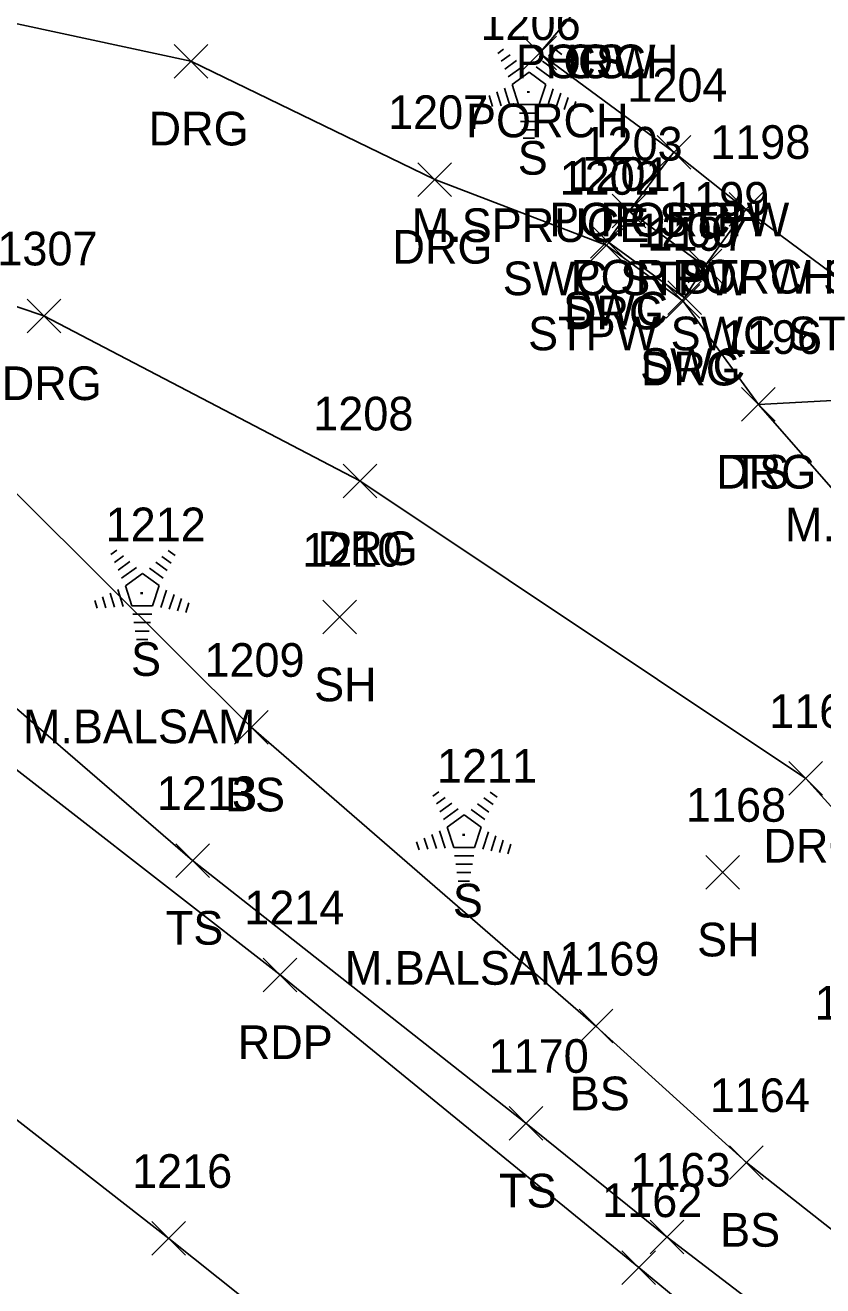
# Model space of a CAD drawing. Extents: x 1537342 to 1542195, y 163002 to 168596.
# Drawn here: x 1541938.8 to 1541986.2, y 163219.8 to 163294.7 of the extents above; entities that cross this region are included whole.
import ezdxf

# ---------------------------------------------------------------- set-up
doc = ezdxf.new("R2010")
doc.units = 0
for name, color, linetype in [('L_A', 7, 'Continuous'), ('L_C', 7, 'Continuous'), ('L_I', 7, 'Continuous'), ('L_TIC', 7, 'Continuous'), ('LBF', 7, 'Continuous'), ('LELB', 7, 'Continuous'), ('LTC', 7, 'Continuous'), ('P_A', 7, 'Continuous'), ('P_I', 7, 'Continuous'), ('P_TIC', 7, 'Continuous'), ('PET', 7, 'Continuous'), ('PRC', 7, 'Continuous'), ('R_A', 7, 'Continuous'), ('R_I', 7, 'Continuous'), ('R_TIC', 7, 'Continuous'), ('RDG', 7, 'Continuous'), ('RSW', 7, 'Continuous')]:
    doc.layers.add(name, color=color, linetype=linetype)

msp = doc.modelspace()

# ---------------------------------------------------------------- linework, layer by layer
at = {"layer": 'L_TIC'}
for points in [[(1541968.383, 163291.994), (1541970.383, 163293.994)], [(1541970.383, 163291.994), (1541968.383, 163293.994)], [(1541976.366, 163286.102), (1541978.366, 163288.102)], [(1541978.366, 163286.102), (1541976.366, 163288.102)], [(1541976.366, 163286.102), (1541978.366, 163288.102)], [(1541978.366, 163286.102), (1541976.366, 163288.102)], [(1541973.702, 163282.614), (1541975.702, 163284.614)], [(1541975.702, 163282.614), (1541973.702, 163284.614)], [(1541980.643, 163282.712), (1541982.643, 163284.712)], [(1541982.643, 163282.712), (1541980.643, 163284.712)], [(1541980.643, 163282.712), (1541982.643, 163284.712)], [(1541982.643, 163282.712), (1541980.643, 163284.712)], [(1541978.208, 163279.339), (1541980.208, 163281.339)], [(1541980.208, 163279.339), (1541978.208, 163281.339)], [(1541981.386, 163271.123), (1541983.386, 163273.123)], [(1541983.386, 163271.123), (1541981.386, 163273.123)], [(1541956.494, 163258.485), (1541958.494, 163260.485)], [(1541958.494, 163258.485), (1541956.494, 163260.485)], [(1541951.245, 163251.94), (1541953.245, 163253.94)], [(1541953.245, 163251.94), (1541951.245, 163253.94)], [(1541947.761, 163244.023), (1541949.761, 163246.023)], [(1541949.761, 163244.023), (1541947.761, 163246.023)], [(1541979.251, 163243.327), (1541981.251, 163245.327)], [(1541981.251, 163243.327), (1541979.251, 163245.327)], [(1541971.727, 163234.185), (1541973.727, 163236.185)], [(1541973.727, 163234.185), (1541971.727, 163236.185)], [(1541967.563, 163228.409), (1541969.563, 163230.409)], [(1541969.563, 163228.409), (1541967.563, 163230.409)], [(1541980.665, 163226.078), (1541982.665, 163228.078)], [(1541982.665, 163226.078), (1541980.665, 163228.078)], [(1541975.951, 163221.645), (1541977.951, 163223.645)], [(1541977.951, 163221.645), (1541975.951, 163223.645)]]:
    msp.add_lwpolyline(points, dxfattribs=at)
at = {"layer": 'LBF'}
for points in [[(1542014.111, 163305.822), (1542002.066, 163289.621), (1542001.763, 163289.132), (1541998.811, 163285.259), (1541998.418, 163284.621), (1541994.003, 163278.598), (1541992.084, 163275.946), (1541981.643, 163283.712), (1541977.366, 163287.102), (1541969.383, 163292.994), (1541972.352, 163296.503)], [(1541981.643, 163283.712), (1541979.208, 163280.339), (1541974.702, 163283.614), (1541977.366, 163287.102)]]:
    msp.add_lwpolyline(points, dxfattribs=at)
at = {"layer": 'LELB'}
for points in [[(1542002.438, 163218.438), (1541992.576, 163218.503), (1541981.665, 163227.078), (1541972.727, 163235.185), (1541952.245, 163252.94), (1541934.224, 163270.875), (1541926.758, 163276.805), (1541931.045, 163280.387), (1541930.665, 163296.396), (1541914.432, 163302.118), (1541899.504, 163302.033), (1541884.497, 163311.998), (1541872.596, 163319.595), (1541857.311, 163324.696)], [(1541994.003, 163278.598), (1541993.771, 163272.734), (1541982.386, 163272.123)], [(1541999.826, 163204.614), (1541992.056, 163211.091), (1541976.951, 163222.645), (1541968.563, 163229.409), (1541948.761, 163245.023), (1541924.199, 163266.22), (1541916.662, 163273.43)]]:
    msp.add_lwpolyline(points, dxfattribs=at)
at = {"layer": 'LTC'}
for p, q in [((1541966.891, 163292.982), (1541967.245, 163293.24)), ((1541967.1, 163292.517), (1541967.63, 163292.901)), ((1541967.31, 163292.051), (1541968.014, 163292.562)), ((1541969.547, 163292.526), (1541970.226, 163292.032)), ((1541969.918, 163292.875), (1541970.467, 163292.475)), ((1541970.289, 163293.223), (1541970.708, 163292.918)), ((1541967.52, 163291.585), (1541968.398, 163292.223)), ((1541967.744, 163291.13), (1541968.756, 163291.865)), ((1541968.756, 163291.865), (1541969.753, 163291.14)), ((1541969.176, 163292.178), (1541969.985, 163291.589)), ((1541967.744, 163291.13), (1541968.131, 163289.937)), ((1541969.753, 163291.14), (1541969.362, 163289.937)), ((1541965.923, 163290.262), (1541966.075, 163289.794)), ((1541966.379, 163290.478), (1541966.59, 163289.827)), ((1541966.834, 163290.695), (1541967.105, 163289.86)), ((1541967.29, 163290.911), (1541967.62, 163289.892)), ((1541970.19, 163290.869), (1541969.852, 163289.83)), ((1541970.635, 163290.619), (1541970.347, 163289.734)), ((1541971.08, 163290.369), (1541970.842, 163289.639)), ((1541969.362, 163289.937), (1541968.131, 163289.937)), ((1541971.524, 163290.118), (1541971.337, 163289.544)), ((1541969.323, 163289.437), (1541968.179, 163289.437)), ((1541969.24, 163288.937), (1541968.251, 163288.937)), ((1541969.156, 163288.437), (1541968.324, 163288.437)), ((1541969.072, 163287.937), (1541968.397, 163287.937)), ((1541943.912, 163263.202), (1541944.267, 163263.459)), ((1541947.311, 163263.442), (1541947.73, 163263.138)), ((1541944.122, 163262.736), (1541944.651, 163263.12)), ((1541944.332, 163262.27), (1541945.035, 163262.782)), ((1541946.569, 163262.745), (1541947.248, 163262.252)), ((1541946.939, 163263.094), (1541947.489, 163262.695)), ((1541944.541, 163261.805), (1541945.419, 163262.443)), ((1541944.766, 163261.35), (1541945.777, 163262.084)), ((1541945.777, 163262.084), (1541946.774, 163261.359)), ((1541946.197, 163262.397), (1541947.007, 163261.808)), ((1541944.311, 163261.13), (1541944.642, 163260.111)), ((1541944.766, 163261.35), (1541945.153, 163260.156)), ((1541946.774, 163261.359), (1541946.383, 163260.156)), ((1541947.212, 163261.088), (1541946.874, 163260.049)), ((1541942.945, 163260.481), (1541943.097, 163260.013)), ((1541943.4, 163260.698), (1541943.612, 163260.046)), ((1541943.856, 163260.914), (1541944.127, 163260.079)), ((1541947.657, 163260.838), (1541947.369, 163259.953)), ((1541948.101, 163260.588), (1541947.864, 163259.858)), ((1541948.545, 163260.338), (1541948.359, 163259.763)), ((1541946.383, 163260.156), (1541945.153, 163260.156)), ((1541946.345, 163259.656), (1541945.2, 163259.656)), ((1541946.261, 163259.156), (1541945.273, 163259.156)), ((1541946.177, 163258.656), (1541945.346, 163258.656)), ((1541946.094, 163258.156), (1541945.419, 163258.156)), ((1541963.036, 163248.851), (1541963.391, 163249.109)), ((1541966.435, 163249.092), (1541966.854, 163248.787)), ((1541963.246, 163248.386), (1541963.775, 163248.77)), ((1541963.456, 163247.92), (1541964.159, 163248.431)), ((1541965.693, 163248.395), (1541966.372, 163247.901)), ((1541966.064, 163248.743), (1541966.613, 163248.344)), ((1541963.665, 163247.454), (1541964.544, 163248.092)), ((1541963.89, 163246.999), (1541964.901, 163247.734)), ((1541964.901, 163247.734), (1541965.899, 163247.009)), ((1541965.321, 163248.047), (1541966.131, 163247.458)), ((1541963.89, 163246.999), (1541964.277, 163245.806)), ((1541965.899, 163247.009), (1541965.507, 163245.806)), ((1541962.069, 163246.13), (1541962.221, 163245.663)), ((1541962.524, 163246.347), (1541962.736, 163245.695)), ((1541962.98, 163246.564), (1541963.251, 163245.728)), ((1541963.435, 163246.78), (1541963.766, 163245.761)), ((1541966.336, 163246.738), (1541965.998, 163245.698)), ((1541966.781, 163246.488), (1541966.493, 163245.603)), ((1541967.225, 163246.238), (1541966.988, 163245.508)), ((1541965.507, 163245.806), (1541964.277, 163245.806)), ((1541965.469, 163245.306), (1541964.324, 163245.306)), ((1541967.669, 163245.987), (1541967.483, 163245.413)), ((1541965.385, 163244.806), (1541964.397, 163244.806)), ((1541965.301, 163244.306), (1541964.47, 163244.306)), ((1541965.218, 163243.806), (1541964.543, 163243.806))]:
    msp.add_line(p, q, dxfattribs=at)
at = {"layer": 'P_TIC'}
for points in [[(1541952.956, 163237.227), (1541954.956, 163239.227)], [(1541954.956, 163237.227), (1541952.956, 163239.227)], [(1541946.346, 163221.574), (1541948.346, 163223.574)], [(1541948.346, 163221.574), (1541946.346, 163223.574)], [(1541974.27, 163219.837), (1541976.27, 163221.837)], [(1541976.27, 163219.837), (1541974.27, 163221.837)]]:
    msp.add_lwpolyline(points, dxfattribs=at)
at = {"layer": 'PET'}
msp.add_lwpolyline([(1542182.456, 163052.966), (1542144.742, 163083.141), (1542111.589, 163110.066), (1542069.863, 163143.449), (1542042.929, 163166.036), (1542014.58, 163189.133), (1541996.517, 163203.324), (1541975.27, 163220.837), (1541953.956, 163238.227), (1541914.853, 163268.66), (1541894.388, 163284.999), (1541874.186, 163298.085), (1541854.833, 163311.466), (1541832.215, 163326.687)], dxfattribs=at)
at = {"layer": 'PRC'}
msp.add_lwpolyline([(1542174.182, 163041.839), (1542135.376, 163070.507), (1542102.151, 163097.417), (1542058.019, 163132.978), (1542032.763, 163153.879), (1541982.814, 163194.284), (1541947.346, 163222.574), (1541904.323, 163256.107), (1541874.287, 163278.529), (1541825.993, 163311.002), (1541814.195, 163318.824)], dxfattribs=at)
at = {"layer": 'R_TIC'}
for points in [[(1541947.659, 163291.511), (1541949.659, 163293.511)], [(1541949.659, 163291.511), (1541947.659, 163293.511)], [(1541962.148, 163284.487), (1541964.148, 163286.487)], [(1541964.148, 163284.487), (1541962.148, 163286.487)], [(1541973.702, 163282.614), (1541975.702, 163284.614)], [(1541975.702, 163282.614), (1541973.702, 163284.614)], [(1541972.411, 163280.81), (1541974.411, 163282.81)], [(1541974.411, 163280.81), (1541972.411, 163282.81)], [(1541972.34, 163280.582), (1541974.34, 163282.582)], [(1541974.34, 163280.582), (1541972.34, 163282.582)], [(1541978.208, 163279.339), (1541980.208, 163281.339)], [(1541980.208, 163279.339), (1541978.208, 163281.339)], [(1541976.907, 163277.251), (1541978.907, 163279.251)], [(1541978.907, 163277.251), (1541976.907, 163279.251)], [(1541976.991, 163277.463), (1541978.991, 163279.463)], [(1541978.991, 163277.463), (1541976.991, 163279.463)], [(1541938.931, 163276.382), (1541940.931, 163278.382)], [(1541940.931, 163276.382), (1541938.931, 163278.382)], [(1541981.386, 163271.123), (1541983.386, 163273.123)], [(1541983.386, 163271.123), (1541981.386, 163273.123)], [(1541957.701, 163266.577), (1541959.701, 163268.577)], [(1541959.701, 163266.577), (1541957.701, 163268.577)], [(1541984.193, 163248.902), (1541986.193, 163250.902)], [(1541986.193, 163248.902), (1541984.193, 163250.902)]]:
    msp.add_lwpolyline(points, dxfattribs=at)
at = {"layer": 'RDG'}
for points in [[(1542017.62, 163206.917), (1542015.196, 163226.11), (1542009.877, 163243.692), (1541994.503, 163258.921), (1541988.515, 163265.136), (1541982.386, 163272.123), (1541977.907, 163278.251), (1541973.34, 163281.582), (1541963.148, 163285.487), (1541948.659, 163292.511), (1541930.665, 163296.396), (1541918.384, 163296.027), (1541913.61, 163296.24), (1541903.895, 163289.032)], [(1542002.848, 163214.546), (1542002.438, 163218.438), (1541997.038, 163236.795), (1541985.193, 163249.902), (1541958.701, 163267.577), (1541939.931, 163277.382), (1541931.045, 163280.387), (1541922.489, 163280.521), (1541918.32, 163277.033)]]:
    msp.add_lwpolyline(points, dxfattribs=at)
at = {"layer": 'RSW'}
msp.add_lwpolyline([(1541979.208, 163280.339), (1541977.991, 163278.463), (1541973.411, 163281.81), (1541974.702, 163283.614)], dxfattribs=at)

# ---------------------------------------------------------------- texts
at = {"layer": 'L_A'}
for s, p in [('PORCH', (1541967.974, 163291.503)), ('HOW', (1541969.737, 163291.503)), ('CS', (1541970.793, 163291.503)), ('PORCH', (1541965.005, 163287.994)), ('S', (1541968.081, 163285.774)), ('POR STPW', (1541969.949, 163282.102)), ('PORCH', (1541972.988, 163282.102)), ('SWC STPW', (1541967.19, 163278.614)), ('POR STPW ST', (1541971.226, 163278.712)), ('PORCH', (1541977.265, 163278.712)), ('STPW SWC ST', (1541968.696, 163275.339)), ('TS', (1541980.796, 163267.123)), ('S', (1541945.103, 163255.994)), ('SH', (1541955.982, 163254.485)), ('BS', (1541950.686, 163247.94)), ('S', (1541964.227, 163241.643)), ('TS', (1541947.17, 163240.023)), ('SH', (1541978.739, 163239.327)), ('BS', (1541971.168, 163230.185)), ('TS', (1541966.973, 163224.409)), ('BS', (1541980.106, 163222.078))]:
    msp.add_text(s, height=2, dxfattribs=at).set_placement(p)
at = {"layer": 'L_C'}
for s, p in [('M.SPRUCE', (1541961.782, 163281.774)), ('M.SPRUCE', (1541983.963, 163263.979)), ('M.BALSAM', (1541938.678, 163251.994)), ('M.BALSAM', (1541957.802, 163237.643))]:
    msp.add_text(s, height=2, dxfattribs=at).set_placement(p)
at = {"layer": 'L_I'}
for s, p in [('1206', (1541965.869, 163293.774)), ('1204', (1541974.594, 163290.102)), ('1204', (1541974.594, 163290.102)), ('1203', (1541971.93, 163286.614)), ('1198', (1541979.518, 163286.712)), ('1198', (1541979.518, 163286.712)), ('1199', (1541977.075, 163283.339)), ('1196', (1541980.206, 163275.123)), ('1212', (1541943.592, 163263.994)), ('1210', (1541955.282, 163262.485)), ('1209', (1541949.465, 163255.94)), ('1211', (1541963.283, 163249.643)), ('1213', (1541946.635, 163248.023)), ('1168', (1541978.078, 163247.327)), ('1169', (1541970.546, 163238.185)), ('1165', (1541985.729, 163235.576)), ('1170', (1541966.351, 163232.409)), ('1164', (1541979.492, 163230.078)), ('1163', (1541974.778, 163225.645))]:
    msp.add_text(s, height=2, dxfattribs=at).set_placement(p)
at = {"layer": 'LTC'}
for p in [(1541968.638, 163290.878), (1541945.66, 163261.098), (1541964.784, 163246.747)]:
    msp.add_text('.', height=1.037, rotation=270, dxfattribs=at).set_placement(p)
at = {"layer": 'P_A'}
msp.add_text('RDP', height=2, dxfattribs=at).set_placement((1541951.444, 163233.227))
at = {"layer": 'P_I'}
for s, p in [('1214', (1541951.83, 163241.227)), ('1216', (1541945.165, 163225.574)), ('1162', (1541973.097, 163223.837))]:
    msp.add_text(s, height=2, dxfattribs=at).set_placement(p)
at = {"layer": 'R_A'}
for s, p in [('DRG', (1541946.147, 163287.511)), ('DRG', (1541960.636, 163280.487)), ('SWC STPW', (1541967.19, 163278.614)), ('SWC', (1541970.773, 163276.81)), ('DRG', (1541970.828, 163276.582)), ('STPW SWC ST', (1541968.696, 163275.339)), ('SWC', (1541975.353, 163273.463)), ('DRG', (1541975.396, 163273.251)), ('DRG', (1541937.419, 163272.382)), ('DRG', (1541979.875, 163267.123)), ('DRG', (1541956.19, 163262.577)), ('DRG', (1541982.681, 163244.902))]:
    msp.add_text(s, height=2, dxfattribs=at).set_placement(p)
at = {"layer": 'R_I'}
for s, p in [('1207', (1541960.377, 163288.487)), ('1203', (1541971.93, 163286.614)), ('1202', (1541970.569, 163284.582)), ('1201', (1541971.207, 163284.81)), ('1199', (1541977.075, 163283.339)), ('1200', (1541975.133, 163281.463)), ('1197', (1541975.782, 163281.251)), ('1307', (1541937.159, 163280.382)), ('1196', (1541980.206, 163275.123)), ('1208', (1541955.93, 163270.577)), ('1167', (1541983.02, 163252.902))]:
    msp.add_text(s, height=2, dxfattribs=at).set_placement(p)

doc.saveas('drawing.dxf')
